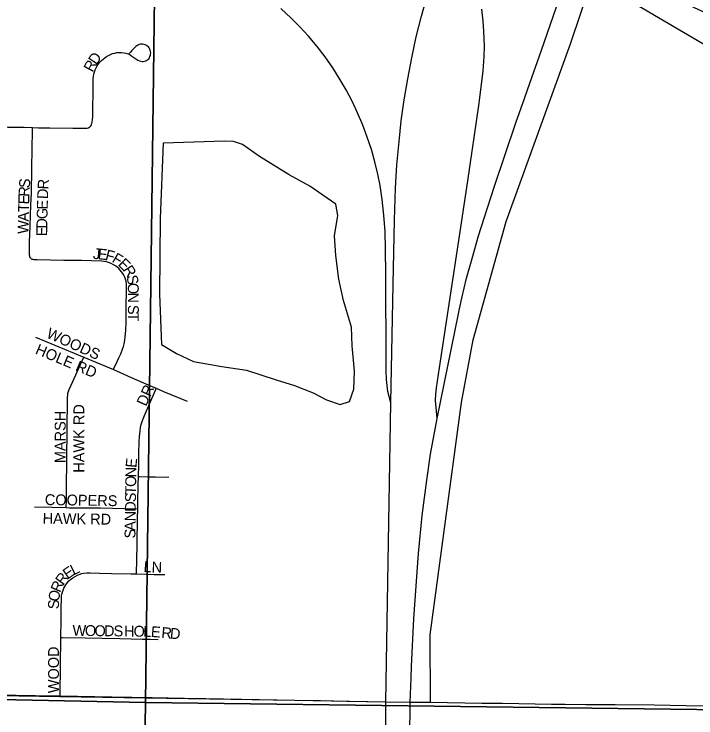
# Model space of a CAD drawing. Extents: x -5.6 to 34, y 0 to 22.
# Drawn here: x 5.047 to 6.304, y 16.786 to 18.084 of the extents above; entities that cross this region are included whole.
import ezdxf

# ---------------------------------------------------------------- set-up
doc = ezdxf.new("R2010")
doc.units = 0
for name, color, linetype in [('GM_X_City_Street', 7, 'Continuous'), ('GM_X_City_Street_Text', 7, 'Continuous'), ('GM_X_Corporation', 7, 'Continuous'), ('GM_X_County_Road', 7, 'Continuous'), ('GM_X_Interstate_Route', 7, 'Continuous'), ('GM_X_Minor_Lake', 7, 'Continuous'), ('GM_X_Section', 7, 'Continuous'), ('SH_Text', 7, 'Continuous')]:
    doc.layers.add(name, color=color, linetype=linetype)

msp = doc.modelspace()

# ---------------------------------------------------------------- linework, layer by layer
at = {"layer": 'GM_X_City_Street'}
for points in [[(5.0814, 17.8746), (5.0921, 17.8743), (5.1131, 17.8738), (5.1557, 17.8734), (5.1748, 17.8732), (5.1786, 17.8732), (5.1823, 17.8736), (5.1843, 17.8742), (5.1853, 17.8746), (5.187, 17.8759), (5.1885, 17.8776), (5.1897, 17.8796), (5.1906, 17.8818), (5.1915, 17.8853), (5.192, 17.889), (5.1923, 17.8941), (5.1927, 17.9137), (5.1931, 17.9348), (5.193, 17.9558), (5.1933, 17.9638), (5.1939, 17.9692), (5.1945, 17.9732), (5.1956, 17.9772), (5.197, 17.9811), (5.1987, 17.9848), (5.2007, 17.9884), (5.203, 17.9918), (5.2055, 17.995), (5.2082, 17.998), (5.2112, 18.0009), (5.2144, 18.0034), (5.2178, 18.0057), (5.2214, 18.0077), (5.2251, 18.0095), (5.229, 18.0108), (5.2329, 18.0119), (5.237, 18.0127), (5.2411, 18.013), (5.2452, 18.013), (5.2493, 18.0126), (5.2534, 18.0118), (5.2574, 18.0105), (5.2611, 18.0086), (5.2646, 18.0064), (5.272, 18.001), (5.2752, 17.999), (5.2785, 17.9975), (5.2808, 17.9969), (5.2831, 17.9966), (5.2855, 17.9966), (5.2877, 17.9969), (5.29, 17.9976), (5.292, 17.9986), (5.2939, 17.9999), (5.2955, 18.0015), (5.2968, 18.0034), (5.2978, 18.0055), (5.2985, 18.0077), (5.299, 18.0101), (5.2991, 18.0125), (5.2989, 18.0148), (5.2984, 18.0171), (5.2975, 18.0192), (5.2963, 18.0213), (5.2949, 18.0231), (5.2932, 18.0247), (5.2913, 18.0261), (5.2892, 18.0272), (5.287, 18.0279), (5.2847, 18.0284), (5.2824, 18.0285), (5.2801, 18.0282), (5.2779, 18.0276), (5.2757, 18.0267), (5.2737, 18.0255), (5.2719, 18.024), (5.2687, 18.0209), (5.2664, 18.0185), (5.2644, 18.0165), (5.2618, 18.0138), (5.2593, 18.0113)], [(4.5981, 17.869), (4.6486, 17.8679), (4.7134, 17.8666), (4.7502, 17.8665), (4.7816, 17.8662), (4.7986, 17.8664), (4.8091, 17.8669), (4.8194, 17.8679), (4.8311, 17.8694), (4.8713, 17.8756), (4.8818, 17.8768), (4.8924, 17.8774), (4.9043, 17.8777), (4.9175, 17.8777), (4.9556, 17.8767), (5.0028, 17.8759), (5.0356, 17.8751), (5.0658, 17.875), (5.0814, 17.8746)], [(5.0787, 17.6325), (5.0779, 17.6336), (5.0773, 17.6345), (5.0766, 17.636), (5.0762, 17.6374), (5.0759, 17.639), (5.0759, 17.6417), (5.0758, 17.6446), (5.0759, 17.6536), (5.076, 17.6624), (5.0768, 17.6927), (5.0783, 17.7321), (5.0793, 17.7531), (5.0803, 17.8005), (5.0813, 17.8694), (5.0814, 17.8746)], [(5.2304, 17.4286), (5.2311, 17.4301), (5.2374, 17.4434), (5.2403, 17.4497), (5.2439, 17.4572), (5.2473, 17.4658), (5.2489, 17.4708), (5.2502, 17.4759), (5.2514, 17.4823), (5.2522, 17.4888), (5.253, 17.5006), (5.2537, 17.5163), (5.2541, 17.5478), (5.2548, 17.5701), (5.2548, 17.5793), (5.2544, 17.5859), (5.2537, 17.5911), (5.2527, 17.5949), (5.2515, 17.5986), (5.2498, 17.6022), (5.2478, 17.6056), (5.2455, 17.6087), (5.2429, 17.6118), (5.2402, 17.6146), (5.2373, 17.6172), (5.2341, 17.6195), (5.2307, 17.6216), (5.2261, 17.624), (5.2212, 17.6259), (5.2174, 17.627), (5.2135, 17.6277), (5.2083, 17.6282), (5.1716, 17.6291), (5.1387, 17.6296), (5.0897, 17.6309), (5.0846, 17.6309), (5.0826, 17.6311), (5.0808, 17.6314), (5.0797, 17.6318), (5.0787, 17.6325)], [(5.0869, 17.488), (5.1759, 17.4511)], [(5.1435, 17.1737), (5.1436, 17.1763), (5.1437, 17.1865), (5.1439, 17.1979), (5.1441, 17.2088), (5.146, 17.3731), (5.1465, 17.3846), (5.1486, 17.3918), (5.1759, 17.4511)], [(5.1759, 17.4511), (5.2304, 17.4286)], [(5.2304, 17.4286), (5.2481, 17.4205), (5.2576, 17.4161), (5.2903, 17.4022), (5.3092, 17.394)], [(5.2767, 17.231), (5.2771, 17.2523), (5.2774, 17.2733), (5.278, 17.2956), (5.2784, 17.3045), (5.2788, 17.3095), (5.2795, 17.315), (5.2805, 17.3215), (5.2817, 17.3269), (5.2833, 17.3323), (5.285, 17.3373), (5.2876, 17.3435), (5.2974, 17.3664), (5.3083, 17.3917), (5.3092, 17.394)], [(5.3092, 17.394), (5.3228, 17.3881), (5.3664, 17.3699)], [(5.2753, 17.1714), (5.2755, 17.1826), (5.2763, 17.2155), (5.2767, 17.231)], [(5.2767, 17.231), (5.2786, 17.2309), (5.2967, 17.2306), (5.308, 17.2305), (5.3274, 17.2301), (5.3327, 17.2302)], [(5.0851, 17.175), (5.1178, 17.1744), (5.1435, 17.1737)], [(5.1435, 17.1737), (5.1492, 17.1736), (5.1784, 17.1733), (5.2068, 17.173), (5.2509, 17.1719), (5.2741, 17.1714), (5.2753, 17.1714)], [(5.2731, 17.0514), (5.2731, 17.0549), (5.2734, 17.075), (5.2742, 17.1078), (5.2749, 17.1538), (5.2753, 17.1714)], [(5.1336, 16.9342), (5.134, 16.9663), (5.1343, 16.9899), (5.1346, 17.0043), (5.135, 17.0107), (5.1356, 17.0144), (5.1365, 17.0181), (5.1377, 17.0216), (5.1392, 17.0251), (5.1409, 17.0284), (5.1429, 17.0316), (5.146, 17.0356), (5.1485, 17.0384), (5.1513, 17.041), (5.1553, 17.044), (5.1596, 17.0468), (5.164, 17.0491), (5.1675, 17.0506), (5.1723, 17.052), (5.176, 17.0527), (5.1811, 17.0533), (5.1875, 17.0534), (5.2047, 17.053), (5.2268, 17.0525), (5.2634, 17.0516), (5.2731, 17.0514)], [(5.2731, 17.0514), (5.291, 17.0508), (5.3054, 17.0505), (5.3252, 17.0506)], [(5.1321, 16.8265), (5.1321, 16.8298), (5.1336, 16.9342)], [(5.1336, 16.9342), (5.1363, 16.9342), (5.1781, 16.9335), (5.2096, 16.9329), (5.2424, 16.9322), (5.2838, 16.9314), (5.2982, 16.9311), (5.313, 16.9308)]]:
    msp.add_lwpolyline(points, dxfattribs=at)
at = {"layer": 'GM_X_Corporation'}
msp.add_lwpolyline([(4.7565, 16.8316), (5.1314, 16.8255), (5.5646, 16.8186), (5.7332, 16.8156), (5.7837, 16.8147), (5.8148, 16.8148), (5.8145, 16.9393), (5.8722, 17.3676), (5.8935, 17.4834), (5.9544, 17.7014), (6.0731, 18.0291), (6.2463, 18.5443)], dxfattribs=at)
at = {"layer": 'GM_X_County_Road'}
for points in [[(4.7565, 16.8316), (4.8009, 16.831), (4.8599, 16.8303), (4.9253, 16.8295), (5.0146, 16.8282), (5.0868, 16.8271), (5.1321, 16.8265)], [(5.1321, 16.8265), (5.1327, 16.8265), (5.2273, 16.8249), (5.3021, 16.8236), (5.3612, 16.8224), (5.4006, 16.8216), (5.5646, 16.8186), (5.6118, 16.8178), (5.6604, 16.817), (5.7328, 16.8156), (5.7776, 16.8149), (5.7809, 16.8148)], [(5.7809, 16.8148), (5.7837, 16.8147), (5.8148, 16.8148)], [(5.8148, 16.8148), (5.9093, 16.8133), (5.9225, 16.8133), (5.9474, 16.8129), (6.038, 16.8113), (6.0629, 16.8113), (6.101, 16.8109), (6.143, 16.8104), (6.155, 16.8104)], [(6.155, 16.8104), (6.227, 16.8099), (6.2861, 16.809), (6.3321, 16.8081), (6.3452, 16.8079)]]:
    msp.add_lwpolyline(points, dxfattribs=at)
at = {"layer": 'GM_X_Interstate_Route'}
for points in [[(5.8663, 17.5308), (5.8682, 17.5403), (5.8729, 17.5602), (5.8815, 17.5966), (5.8916, 17.6333), (5.9035, 17.675), (5.9135, 17.7077), (5.9326, 17.7665), (5.9723, 17.8834), (5.9879, 17.9281), (5.9979, 17.9566), (6.0193, 18.0173), (6.0631, 18.1439)], [(5.7332, 16.7226), (5.7328, 16.8156), (5.7416, 17.3668), (5.746, 17.5854), (5.7484, 17.7035), (5.7504, 17.7625), (5.753, 17.8057), (5.7568, 17.8489), (5.7609, 17.8867), (5.7664, 17.9256), (5.7728, 17.9644), (5.7803, 18.0031), (5.7887, 18.0416), (5.7982, 18.0799), (5.8086, 18.1179)], [(5.7416, 17.3668), (5.736, 17.3879), (5.7338, 17.4102), (5.7329, 17.4257), (5.7329, 17.44), (5.7327, 17.6042), (5.7322, 17.6502), (5.731, 17.683), (5.729, 17.7131), (5.7258, 17.7419), (5.7218, 17.7678), (5.7177, 17.7884), (5.7122, 17.8114), (5.7058, 17.8342), (5.6984, 17.8566), (5.6901, 17.8788), (5.6803, 17.9017), (5.6702, 17.9231), (5.6592, 17.944), (5.6467, 17.9656), (5.6347, 17.9845), (5.6204, 18.0049), (5.606, 18.0237), (5.5901, 18.0429), (5.5741, 18.0603), (5.5583, 18.0761), (5.5391, 18.094)], [(5.8273, 17.3382), (5.8252, 17.3583), (5.8239, 17.3712), (5.8247, 17.3826), (5.8256, 17.3944), (5.8334, 17.4437), (5.8596, 17.6177), (5.8701, 17.6865), (5.8836, 17.7761), (5.904, 17.9151), (5.9085, 17.9489), (5.9117, 17.9789), (5.9135, 18.0051), (5.9142, 18.0248), (5.9134, 18.0523), (5.912, 18.0706), (5.9092, 18.0928)], [(5.8273, 17.3382), (5.8663, 17.5308)], [(5.7792, 16.8594), (5.78, 16.8805), (5.7839, 16.9691), (5.7925, 17.0894), (5.7995, 17.1593), (5.8081, 17.2241), (5.815, 17.2723), (5.8273, 17.3382)], [(5.7776, 16.8149), (5.7792, 16.8594)], [(5.745, 14.6938), (5.7503, 15.0391), (5.7536, 15.2492), (5.7563, 15.4093), (5.7568, 15.4474), (5.7603, 15.6811), (5.7622, 15.7914), (5.7627, 15.8203), (5.7632, 15.8544), (5.7657, 16.0028), (5.7668, 16.0645), (5.768, 16.1472), (5.7685, 16.1944), (5.7689, 16.2207), (5.7699, 16.3126), (5.7707, 16.3717), (5.7717, 16.4321), (5.7732, 16.5148), (5.7746, 16.5989), (5.7769, 16.7485), (5.7776, 16.8149)]]:
    msp.add_lwpolyline(points, dxfattribs=at)
at = {"layer": 'GM_X_Minor_Lake'}
for points in [[(5.4349, 17.8493), (5.3223, 17.8456), (5.3165, 17.707), (5.3155, 17.5674), (5.3188, 17.4743), (5.3464, 17.4576), (5.378, 17.4432), (5.4304, 17.4339)], [(5.4304, 17.4339), (5.4754, 17.427), (5.5303, 17.4095), (5.5644, 17.3986), (5.5985, 17.3854), (5.6231, 17.3722), (5.6485, 17.3639), (5.6654, 17.3693), (5.6736, 17.3924), (5.6749, 17.4253), (5.6707, 17.4718), (5.6695, 17.5063), (5.6542, 17.5554), (5.646, 17.5948), (5.6401, 17.6389), (5.6382, 17.675), (5.6443, 17.7126), (5.6406, 17.7335), (5.5923, 17.7662), (5.5543, 17.7875), (5.4997, 17.821), (5.4681, 17.8431), (5.4516, 17.8488), (5.4349, 17.8493)]]:
    msp.add_lwpolyline(points, dxfattribs=at)
at = {"layer": 'GM_X_Section'}
for points in [[(3.1889, 18.9888), (5.3166, 18.9352), (5.2895, 16.8144), (3.1401, 16.8587)], [(5.3166, 18.9352), (7.4578, 18.9294), (7.4183, 16.7871), (5.2895, 16.8144)], [(3.1401, 16.8587), (5.2895, 16.8144), (5.2575, 14.6921), (3.0791, 14.7168)], [(5.2895, 16.8144), (7.4183, 16.7871), (7.3798, 14.6657), (5.2575, 14.6921)]]:
    msp.add_lwpolyline(points, close=True, dxfattribs=at)
at = {"layer": 'SH_Text'}
msp.add_lwpolyline([(9.909, 15.9208), (5.8309, 18.3146), (9.909, 16.4208)], close=True, dxfattribs=at)

# ---------------------------------------------------------------- texts
at = {"layer": 'GM_X_City_Street_Text'}
for s, rotation, p in [('D', 55.9947, (5.1991, 17.9888)), ('R', 61.9575, (5.1919, 17.9753)), ('S', 86.0351, (5.0761, 17.7624)), ('R', 86.5252, (5.1104, 17.7599)), ('R', 87.157, (5.0753, 17.7466)), ('D', 87.726, (5.1097, 17.7424)), ('E', 88.663, (5.075, 17.7327)), ('T', 88.6341, (5.0746, 17.7186)), ('E', 88.4422, (5.1092, 17.7231)), ('A', 88.6449, (5.0742, 17.701)), ('G', 88.7104, (5.1088, 17.7055)), ('W', 88.6549, (5.0737, 17.6782)), ('D', 88.7429, (5.1084, 17.688)), ('E', 88.716, (5.1081, 17.6739)), ('J', 354.9678, (5.1921, 17.6325)), ('E', 354.0882, (5.2008, 17.6318)), ('F', 345.6457, (5.214, 17.6305)), ('F', 329.5095, (5.2263, 17.6275)), ('E', 316.3718, (5.2375, 17.6211)), ('R', 302.5923, (5.2469, 17.6124)), ('S', 279.4668, (5.2546, 17.601)), ('O', 271.0055, (5.2569, 17.5879)), ('N', 270, (5.2572, 17.5704)), ('S', 269.9956, (5.2572, 17.5475)), ('T', 269.9956, (5.2572, 17.5334)), ('WOODS', 335.925, (5.1054, 17.4879)), ('HOLE RD', 337.3074, (5.085, 17.458)), ('DR', 66.0307, (5.2905, 17.3593)), ('HAWK RD', 90, (5.1767, 17.2381)), ('MARSH', 90, (5.1423, 17.2557)), ('E', 84.8575, (5.2727, 17.2465)), ('N', 89.137, (5.2725, 17.2293)), ('O', 89.1256, (5.2722, 17.2117)), ('T', 89.1257, (5.272, 17.1976)), ('COOPERS', 359.0898, (5.1039, 17.1785)), ('S', 89.1412, (5.2718, 17.1835)), ('D', 89.1256, (5.2715, 17.1659)), ('HAWK RD', 359.1322, (5.0998, 17.1441)), ('N', 89.1256, (5.2713, 17.1483)), ('A', 89.137, (5.271, 17.1307)), ('S', 89.1257, (5.2708, 17.1167)), ('L', 26.0519, (5.1568, 17.0485)), ('L', 355.4315, (5.2854, 17.0553)), ('N', 358.4209, (5.3006, 17.0541)), ('E', 34.804, (5.1459, 17.0408)), ('R', 53.5138, (5.1377, 17.0293)), ('R', 66.4443, (5.132, 17.0158)), ('O', 82.4169, (5.1301, 16.9998)), ('S', 89.4262, (5.13, 16.9863)), ('W', 359.2771, (5.1549, 16.9374)), ('O', 359.272, (5.1778, 16.9371)), ('O', 359.2786, (5.1954, 16.9368)), ('D', 359.2568, (5.213, 16.9366)), ('S', 359.2795, (5.2306, 16.9364)), ('H', 359.272, (5.2499, 16.9361)), ('O', 359.272, (5.2675, 16.9359)), ('L', 358.1964, (5.285, 16.9357)), ('E', 355.5699, (5.2989, 16.9353)), ('R', 354.7968, (5.3181, 16.9337)), ('D', 354.8124, (5.3339, 16.9323)), ('WOOD', 90, (5.13, 16.8315))]:
    msp.add_text(s, height=0.02, rotation=rotation, dxfattribs=at).set_placement(p)

doc.saveas('drawing.dxf')
